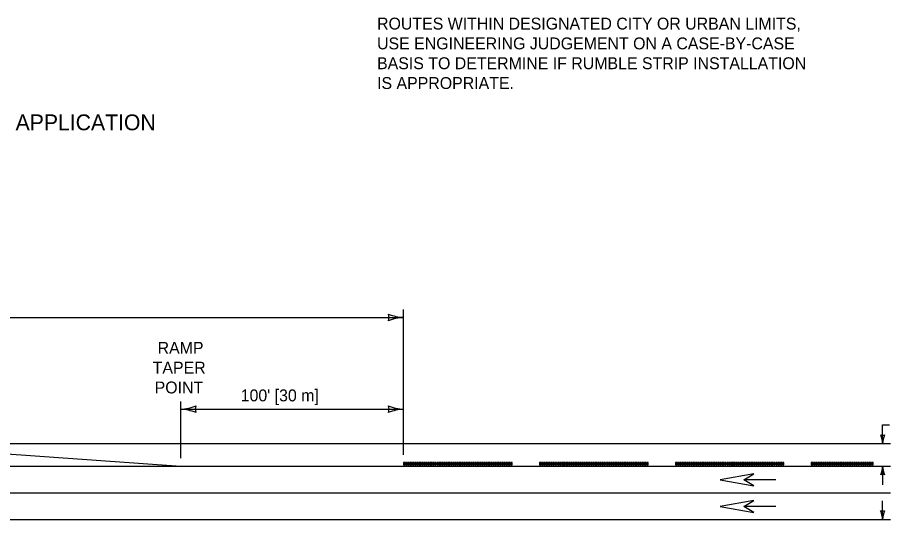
# Model space of a CAD drawing. Extents: x 49991.4 to 50021, y 49987.6 to 50011.4.
# Drawn here: x 50008.031 to 50012.439, y 49990.5 to 49993.033 of the extents above; entities that cross this region are included whole.
import ezdxf

# ---------------------------------------------------------------- set-up
doc = ezdxf.new("R2010")
doc.units = 0
for name, color, linetype in [('Level 1', 7, 'Continuous'), ('Level 2', 7, 'Continuous'), ('Level 3', 7, 'Continuous')]:
    doc.layers.add(name, color=color, linetype=linetype)

msp = doc.modelspace()

# ---------------------------------------------------------------- linework, layer by layer
at = {"layer": 'Level 1'}
for p, q in [((50007.0002, 49990.8996), (50008.8555, 49990.7698)), ((50012.4393, 49990.8823), (50007.8935, 49990.8823)), ((50005.9012, 49990.7698), (50012.4393, 49990.7698)), ((50011.8604, 49990.6996), (50011.6978, 49990.6996)), ((50011.8604, 49990.6995), (50011.6978, 49990.6995)), ((50005.9012, 49990.6348), (50012.4393, 49990.6348)), ((50011.8604, 49990.5662), (50011.6978, 49990.5662)), ((50011.8604, 49990.5661), (50011.6978, 49990.5661)), ((50005.9012, 49990.4998), (50012.4393, 49990.4998))]:
    msp.add_line(p, q, dxfattribs=at)
for points in [[(50009.9885, 49990.7868), (50009.9805, 49990.7868), (50009.9805, 49990.7756), (50009.9885, 49990.7756)], [(50009.9997, 49990.7868), (50009.9919, 49990.7868), (50009.9919, 49990.7756), (50009.9997, 49990.7756)], [(50010.0109, 49990.7868), (50010.0031, 49990.7868), (50010.0031, 49990.7756), (50010.0109, 49990.7756)], [(50010.0222, 49990.7868), (50010.0143, 49990.7868), (50010.0143, 49990.7756), (50010.0222, 49990.7756)], [(50010.0335, 49990.7868), (50010.0255, 49990.7868), (50010.0255, 49990.7756), (50010.0335, 49990.7756)], [(50010.0447, 49990.7868), (50010.0369, 49990.7868), (50010.0369, 49990.7756), (50010.0447, 49990.7756)], [(50010.0559, 49990.7868), (50010.0481, 49990.7868), (50010.0481, 49990.7756), (50010.0559, 49990.7756)], [(50010.0672, 49990.7868), (50010.0593, 49990.7868), (50010.0593, 49990.7756), (50010.0672, 49990.7756)], [(50010.0785, 49990.7868), (50010.0705, 49990.7868), (50010.0705, 49990.7756), (50010.0785, 49990.7756)], [(50010.0897, 49990.7868), (50010.0819, 49990.7868), (50010.0819, 49990.7756), (50010.0897, 49990.7756)], [(50010.1009, 49990.7868), (50010.0931, 49990.7868), (50010.0931, 49990.7756), (50010.1009, 49990.7756)], [(50010.1122, 49990.7868), (50010.1043, 49990.7868), (50010.1043, 49990.7756), (50010.1122, 49990.7756)], [(50010.1235, 49990.7868), (50010.1155, 49990.7868), (50010.1155, 49990.7756), (50010.1235, 49990.7756)], [(50010.1347, 49990.7868), (50010.1269, 49990.7868), (50010.1269, 49990.7756), (50010.1347, 49990.7756)], [(50010.1459, 49990.7868), (50010.1381, 49990.7868), (50010.1381, 49990.7756), (50010.1459, 49990.7756)], [(50010.1572, 49990.7868), (50010.1493, 49990.7868), (50010.1493, 49990.7756), (50010.1572, 49990.7756)], [(50010.1685, 49990.7868), (50010.1605, 49990.7868), (50010.1605, 49990.7756), (50010.1685, 49990.7756)], [(50010.1797, 49990.7868), (50010.1719, 49990.7868), (50010.1719, 49990.7756), (50010.1797, 49990.7756)], [(50010.1909, 49990.7868), (50010.1831, 49990.7868), (50010.1831, 49990.7756), (50010.1909, 49990.7756)], [(50010.2022, 49990.7868), (50010.1943, 49990.7868), (50010.1943, 49990.7756), (50010.2022, 49990.7756)], [(50010.2135, 49990.7868), (50010.2055, 49990.7868), (50010.2055, 49990.7756), (50010.2135, 49990.7756)], [(50010.2247, 49990.7868), (50010.2169, 49990.7868), (50010.2169, 49990.7756), (50010.2247, 49990.7756)], [(50010.2359, 49990.7868), (50010.2281, 49990.7868), (50010.2281, 49990.7756), (50010.2359, 49990.7756)], [(50010.2472, 49990.7868), (50010.2393, 49990.7868), (50010.2393, 49990.7756), (50010.2472, 49990.7756)], [(50010.2585, 49990.7868), (50010.2505, 49990.7868), (50010.2505, 49990.7756), (50010.2585, 49990.7756)], [(50010.2697, 49990.7868), (50010.2619, 49990.7868), (50010.2619, 49990.7756), (50010.2697, 49990.7756)], [(50010.2809, 49990.7868), (50010.2731, 49990.7868), (50010.2731, 49990.7756), (50010.2809, 49990.7756)], [(50010.2922, 49990.7868), (50010.2843, 49990.7868), (50010.2843, 49990.7756), (50010.2922, 49990.7756)], [(50010.3035, 49990.7868), (50010.2955, 49990.7868), (50010.2955, 49990.7756), (50010.3035, 49990.7756)], [(50010.3147, 49990.7868), (50010.3069, 49990.7868), (50010.3069, 49990.7756), (50010.3147, 49990.7756)], [(50010.3259, 49990.7868), (50010.3181, 49990.7868), (50010.3181, 49990.7756), (50010.3259, 49990.7756)], [(50010.3372, 49990.7868), (50010.3293, 49990.7868), (50010.3293, 49990.7756), (50010.3372, 49990.7756)], [(50010.3485, 49990.7868), (50010.3405, 49990.7868), (50010.3405, 49990.7756), (50010.3485, 49990.7756)], [(50010.3597, 49990.7868), (50010.3519, 49990.7868), (50010.3519, 49990.7756), (50010.3597, 49990.7756)], [(50010.3709, 49990.7868), (50010.3631, 49990.7868), (50010.3631, 49990.7756), (50010.3709, 49990.7756)], [(50010.3822, 49990.7868), (50010.3743, 49990.7868), (50010.3743, 49990.7756), (50010.3822, 49990.7756)], [(50010.3935, 49990.7868), (50010.3855, 49990.7868), (50010.3855, 49990.7756), (50010.3935, 49990.7756)], [(50010.4047, 49990.7868), (50010.3969, 49990.7868), (50010.3969, 49990.7756), (50010.4047, 49990.7756)], [(50010.4159, 49990.7868), (50010.4081, 49990.7868), (50010.4081, 49990.7756), (50010.4159, 49990.7756)], [(50010.4272, 49990.7868), (50010.4193, 49990.7868), (50010.4193, 49990.7756), (50010.4272, 49990.7756)], [(50010.4385, 49990.7868), (50010.4305, 49990.7868), (50010.4305, 49990.7756), (50010.4385, 49990.7756)], [(50010.4497, 49990.7868), (50010.4419, 49990.7868), (50010.4419, 49990.7756), (50010.4497, 49990.7756)], [(50010.4609, 49990.7868), (50010.4531, 49990.7868), (50010.4531, 49990.7756), (50010.4609, 49990.7756)], [(50010.4722, 49990.7868), (50010.4643, 49990.7868), (50010.4643, 49990.7756), (50010.4722, 49990.7756)], [(50010.4835, 49990.7868), (50010.4755, 49990.7868), (50010.4755, 49990.7756), (50010.4835, 49990.7756)], [(50010.4947, 49990.7868), (50010.4869, 49990.7868), (50010.4869, 49990.7756), (50010.4947, 49990.7756)], [(50010.5059, 49990.7868), (50010.4981, 49990.7868), (50010.4981, 49990.7756), (50010.5059, 49990.7756)], [(50010.5172, 49990.7868), (50010.5093, 49990.7868), (50010.5093, 49990.7756), (50010.5172, 49990.7756)], [(50010.5285, 49990.7868), (50010.5205, 49990.7868), (50010.5205, 49990.7756), (50010.5285, 49990.7756)], [(50010.6747, 49990.7868), (50010.6669, 49990.7868), (50010.6669, 49990.7756), (50010.6747, 49990.7756)], [(50010.6859, 49990.7868), (50010.6781, 49990.7868), (50010.6781, 49990.7756), (50010.6859, 49990.7756)], [(50010.6972, 49990.7868), (50010.6893, 49990.7868), (50010.6893, 49990.7756), (50010.6972, 49990.7756)], [(50010.7085, 49990.7868), (50010.7005, 49990.7868), (50010.7005, 49990.7756), (50010.7085, 49990.7756)], [(50010.7197, 49990.7868), (50010.7119, 49990.7868), (50010.7119, 49990.7756), (50010.7197, 49990.7756)], [(50010.7309, 49990.7868), (50010.7231, 49990.7868), (50010.7231, 49990.7756), (50010.7309, 49990.7756)], [(50010.7422, 49990.7868), (50010.7343, 49990.7868), (50010.7343, 49990.7756), (50010.7422, 49990.7756)], [(50010.7535, 49990.7868), (50010.7455, 49990.7868), (50010.7455, 49990.7756), (50010.7535, 49990.7756)], [(50010.7647, 49990.7868), (50010.7569, 49990.7868), (50010.7569, 49990.7756), (50010.7647, 49990.7756)], [(50010.7759, 49990.7868), (50010.7681, 49990.7868), (50010.7681, 49990.7756), (50010.7759, 49990.7756)], [(50010.7872, 49990.7868), (50010.7793, 49990.7868), (50010.7793, 49990.7756), (50010.7872, 49990.7756)], [(50010.7985, 49990.7868), (50010.7905, 49990.7868), (50010.7905, 49990.7756), (50010.7985, 49990.7756)], [(50010.8097, 49990.7868), (50010.8019, 49990.7868), (50010.8019, 49990.7756), (50010.8097, 49990.7756)], [(50010.8209, 49990.7868), (50010.8131, 49990.7868), (50010.8131, 49990.7756), (50010.8209, 49990.7756)], [(50010.8322, 49990.7868), (50010.8243, 49990.7868), (50010.8243, 49990.7756), (50010.8322, 49990.7756)], [(50010.8435, 49990.7868), (50010.8355, 49990.7868), (50010.8355, 49990.7756), (50010.8435, 49990.7756)], [(50010.8547, 49990.7868), (50010.8469, 49990.7868), (50010.8469, 49990.7756), (50010.8547, 49990.7756)], [(50010.8659, 49990.7868), (50010.8581, 49990.7868), (50010.8581, 49990.7756), (50010.8659, 49990.7756)], [(50010.8772, 49990.7868), (50010.8693, 49990.7868), (50010.8693, 49990.7756), (50010.8772, 49990.7756)], [(50010.8885, 49990.7868), (50010.8805, 49990.7868), (50010.8805, 49990.7756), (50010.8885, 49990.7756)], [(50010.8997, 49990.7868), (50010.8919, 49990.7868), (50010.8919, 49990.7756), (50010.8997, 49990.7756)], [(50010.9109, 49990.7868), (50010.9031, 49990.7868), (50010.9031, 49990.7756), (50010.9109, 49990.7756)], [(50010.9222, 49990.7868), (50010.9143, 49990.7868), (50010.9143, 49990.7756), (50010.9222, 49990.7756)], [(50010.9335, 49990.7868), (50010.9255, 49990.7868), (50010.9255, 49990.7756), (50010.9335, 49990.7756)], [(50010.9447, 49990.7868), (50010.9369, 49990.7868), (50010.9369, 49990.7756), (50010.9447, 49990.7756)], [(50010.9559, 49990.7868), (50010.9481, 49990.7868), (50010.9481, 49990.7756), (50010.9559, 49990.7756)], [(50010.9672, 49990.7868), (50010.9593, 49990.7868), (50010.9593, 49990.7756), (50010.9672, 49990.7756)], [(50010.9785, 49990.7868), (50010.9705, 49990.7868), (50010.9705, 49990.7756), (50010.9785, 49990.7756)], [(50010.9897, 49990.7868), (50010.9819, 49990.7868), (50010.9819, 49990.7756), (50010.9897, 49990.7756)], [(50011.0009, 49990.7868), (50010.9931, 49990.7868), (50010.9931, 49990.7756), (50011.0009, 49990.7756)], [(50011.0122, 49990.7868), (50011.0043, 49990.7868), (50011.0043, 49990.7756), (50011.0122, 49990.7756)], [(50011.0235, 49990.7868), (50011.0155, 49990.7868), (50011.0155, 49990.7756), (50011.0235, 49990.7756)], [(50011.0347, 49990.7868), (50011.0269, 49990.7868), (50011.0269, 49990.7756), (50011.0347, 49990.7756)], [(50011.0459, 49990.7868), (50011.0381, 49990.7868), (50011.0381, 49990.7756), (50011.0459, 49990.7756)], [(50011.0572, 49990.7868), (50011.0493, 49990.7868), (50011.0493, 49990.7756), (50011.0572, 49990.7756)], [(50011.0685, 49990.7868), (50011.0605, 49990.7868), (50011.0605, 49990.7756), (50011.0685, 49990.7756)], [(50011.0797, 49990.7868), (50011.0719, 49990.7868), (50011.0719, 49990.7756), (50011.0797, 49990.7756)], [(50011.0909, 49990.7868), (50011.0831, 49990.7868), (50011.0831, 49990.7756), (50011.0909, 49990.7756)], [(50011.1022, 49990.7868), (50011.0943, 49990.7868), (50011.0943, 49990.7756), (50011.1022, 49990.7756)], [(50011.1135, 49990.7868), (50011.1055, 49990.7868), (50011.1055, 49990.7756), (50011.1135, 49990.7756)], [(50011.1247, 49990.7868), (50011.1169, 49990.7868), (50011.1169, 49990.7756), (50011.1247, 49990.7756)], [(50011.1359, 49990.7868), (50011.1281, 49990.7868), (50011.1281, 49990.7756), (50011.1359, 49990.7756)], [(50011.1472, 49990.7868), (50011.1393, 49990.7868), (50011.1393, 49990.7756), (50011.1472, 49990.7756)], [(50011.1585, 49990.7868), (50011.1505, 49990.7868), (50011.1505, 49990.7756), (50011.1585, 49990.7756)], [(50011.1697, 49990.7868), (50011.1619, 49990.7868), (50011.1619, 49990.7756), (50011.1697, 49990.7756)], [(50011.1809, 49990.7868), (50011.1731, 49990.7868), (50011.1731, 49990.7756), (50011.1809, 49990.7756)], [(50011.1922, 49990.7868), (50011.1843, 49990.7868), (50011.1843, 49990.7756), (50011.1922, 49990.7756)], [(50011.2035, 49990.7868), (50011.1955, 49990.7868), (50011.1955, 49990.7756), (50011.2035, 49990.7756)], [(50011.2147, 49990.7868), (50011.2069, 49990.7868), (50011.2069, 49990.7756), (50011.2147, 49990.7756)], [(50011.3609, 49990.7868), (50011.3531, 49990.7868), (50011.3531, 49990.7756), (50011.3609, 49990.7756)], [(50011.3722, 49990.7868), (50011.3643, 49990.7868), (50011.3643, 49990.7756), (50011.3722, 49990.7756)], [(50011.3835, 49990.7868), (50011.3755, 49990.7868), (50011.3755, 49990.7756), (50011.3835, 49990.7756)], [(50011.3947, 49990.7868), (50011.3869, 49990.7868), (50011.3869, 49990.7756), (50011.3947, 49990.7756)], [(50011.4059, 49990.7868), (50011.3981, 49990.7868), (50011.3981, 49990.7756), (50011.4059, 49990.7756)], [(50011.4172, 49990.7868), (50011.4093, 49990.7868), (50011.4093, 49990.7756), (50011.4172, 49990.7756)], [(50011.4285, 49990.7868), (50011.4205, 49990.7868), (50011.4205, 49990.7756), (50011.4285, 49990.7756)], [(50011.4397, 49990.7868), (50011.4319, 49990.7868), (50011.4319, 49990.7756), (50011.4397, 49990.7756)], [(50011.4509, 49990.7868), (50011.4431, 49990.7868), (50011.4431, 49990.7756), (50011.4509, 49990.7756)], [(50011.4622, 49990.7868), (50011.4543, 49990.7868), (50011.4543, 49990.7756), (50011.4622, 49990.7756)], [(50011.4735, 49990.7868), (50011.4655, 49990.7868), (50011.4655, 49990.7756), (50011.4735, 49990.7756)], [(50011.4847, 49990.7868), (50011.4769, 49990.7868), (50011.4769, 49990.7756), (50011.4847, 49990.7756)], [(50011.4959, 49990.7868), (50011.4881, 49990.7868), (50011.4881, 49990.7756), (50011.4959, 49990.7756)], [(50011.5072, 49990.7868), (50011.4993, 49990.7868), (50011.4993, 49990.7756), (50011.5072, 49990.7756)], [(50011.5185, 49990.7868), (50011.5105, 49990.7868), (50011.5105, 49990.7756), (50011.5185, 49990.7756)], [(50011.5297, 49990.7868), (50011.5219, 49990.7868), (50011.5219, 49990.7756), (50011.5297, 49990.7756)], [(50011.5409, 49990.7868), (50011.5331, 49990.7868), (50011.5331, 49990.7756), (50011.5409, 49990.7756)], [(50011.5522, 49990.7868), (50011.5443, 49990.7868), (50011.5443, 49990.7756), (50011.5522, 49990.7756)], [(50011.5635, 49990.7868), (50011.5555, 49990.7868), (50011.5555, 49990.7756), (50011.5635, 49990.7756)], [(50011.5747, 49990.7868), (50011.5669, 49990.7868), (50011.5669, 49990.7756), (50011.5747, 49990.7756)], [(50011.5859, 49990.7868), (50011.5781, 49990.7868), (50011.5781, 49990.7756), (50011.5859, 49990.7756)], [(50011.5972, 49990.7868), (50011.5893, 49990.7868), (50011.5893, 49990.7756), (50011.5972, 49990.7756)], [(50011.6085, 49990.7868), (50011.6005, 49990.7868), (50011.6005, 49990.7756), (50011.6085, 49990.7756)], [(50011.6197, 49990.7868), (50011.6119, 49990.7868), (50011.6119, 49990.7756), (50011.6197, 49990.7756)], [(50011.6309, 49990.7868), (50011.6231, 49990.7868), (50011.6231, 49990.7756), (50011.6309, 49990.7756)], [(50011.6422, 49990.7868), (50011.6343, 49990.7868), (50011.6343, 49990.7756), (50011.6422, 49990.7756)], [(50011.6535, 49990.7868), (50011.6455, 49990.7868), (50011.6455, 49990.7756), (50011.6535, 49990.7756)], [(50011.6647, 49990.7868), (50011.6569, 49990.7868), (50011.6569, 49990.7756), (50011.6647, 49990.7756)], [(50011.6759, 49990.7868), (50011.6681, 49990.7868), (50011.6681, 49990.7756), (50011.6759, 49990.7756)], [(50011.6872, 49990.7868), (50011.6793, 49990.7868), (50011.6793, 49990.7756), (50011.6872, 49990.7756)], [(50011.6985, 49990.7868), (50011.6905, 49990.7868), (50011.6905, 49990.7756), (50011.6985, 49990.7756)], [(50011.7097, 49990.7868), (50011.7019, 49990.7868), (50011.7019, 49990.7756), (50011.7097, 49990.7756)], [(50011.7209, 49990.7868), (50011.7131, 49990.7868), (50011.7131, 49990.7756), (50011.7209, 49990.7756)], [(50011.7322, 49990.7868), (50011.7243, 49990.7868), (50011.7243, 49990.7756), (50011.7322, 49990.7756)], [(50011.7435, 49990.7868), (50011.7355, 49990.7868), (50011.7355, 49990.7756), (50011.7435, 49990.7756)], [(50011.7547, 49990.7868), (50011.7469, 49990.7868), (50011.7469, 49990.7756), (50011.7547, 49990.7756)], [(50011.7659, 49990.7868), (50011.7581, 49990.7868), (50011.7581, 49990.7756), (50011.7659, 49990.7756)], [(50011.7772, 49990.7868), (50011.7693, 49990.7868), (50011.7693, 49990.7756), (50011.7772, 49990.7756)], [(50011.7885, 49990.7868), (50011.7805, 49990.7868), (50011.7805, 49990.7756), (50011.7885, 49990.7756)], [(50011.7997, 49990.7868), (50011.7919, 49990.7868), (50011.7919, 49990.7756), (50011.7997, 49990.7756)], [(50011.8109, 49990.7868), (50011.8031, 49990.7868), (50011.8031, 49990.7756), (50011.8109, 49990.7756)], [(50011.8222, 49990.7868), (50011.8143, 49990.7868), (50011.8143, 49990.7756), (50011.8222, 49990.7756)], [(50011.8335, 49990.7868), (50011.8255, 49990.7868), (50011.8255, 49990.7756), (50011.8335, 49990.7756)], [(50011.8447, 49990.7868), (50011.8369, 49990.7868), (50011.8369, 49990.7756), (50011.8447, 49990.7756)], [(50011.8559, 49990.7868), (50011.8481, 49990.7868), (50011.8481, 49990.7756), (50011.8559, 49990.7756)], [(50011.8672, 49990.7868), (50011.8593, 49990.7868), (50011.8593, 49990.7756), (50011.8672, 49990.7756)], [(50011.8785, 49990.7868), (50011.8705, 49990.7868), (50011.8705, 49990.7756), (50011.8785, 49990.7756)], [(50011.8897, 49990.7868), (50011.8819, 49990.7868), (50011.8819, 49990.7756), (50011.8897, 49990.7756)], [(50011.9009, 49990.7868), (50011.8931, 49990.7868), (50011.8931, 49990.7756), (50011.9009, 49990.7756)], [(50012.0472, 49990.7868), (50012.0393, 49990.7868), (50012.0393, 49990.7756), (50012.0472, 49990.7756)], [(50012.0585, 49990.7868), (50012.0505, 49990.7868), (50012.0505, 49990.7756), (50012.0585, 49990.7756)], [(50012.0697, 49990.7868), (50012.0619, 49990.7868), (50012.0619, 49990.7756), (50012.0697, 49990.7756)], [(50012.0809, 49990.7868), (50012.0731, 49990.7868), (50012.0731, 49990.7756), (50012.0809, 49990.7756)], [(50012.0922, 49990.7868), (50012.0843, 49990.7868), (50012.0843, 49990.7756), (50012.0922, 49990.7756)], [(50012.1035, 49990.7868), (50012.0955, 49990.7868), (50012.0955, 49990.7756), (50012.1035, 49990.7756)], [(50012.1147, 49990.7868), (50012.1069, 49990.7868), (50012.1069, 49990.7756), (50012.1147, 49990.7756)], [(50012.1259, 49990.7868), (50012.1181, 49990.7868), (50012.1181, 49990.7756), (50012.1259, 49990.7756)], [(50012.1372, 49990.7868), (50012.1293, 49990.7868), (50012.1293, 49990.7756), (50012.1372, 49990.7756)], [(50012.1485, 49990.7868), (50012.1405, 49990.7868), (50012.1405, 49990.7756), (50012.1485, 49990.7756)], [(50012.1597, 49990.7868), (50012.1519, 49990.7868), (50012.1519, 49990.7756), (50012.1597, 49990.7756)], [(50012.1709, 49990.7868), (50012.1631, 49990.7868), (50012.1631, 49990.7756), (50012.1709, 49990.7756)], [(50012.1822, 49990.7868), (50012.1743, 49990.7868), (50012.1743, 49990.7756), (50012.1822, 49990.7756)], [(50012.1935, 49990.7868), (50012.1855, 49990.7868), (50012.1855, 49990.7756), (50012.1935, 49990.7756)], [(50012.2047, 49990.7868), (50012.1969, 49990.7868), (50012.1969, 49990.7756), (50012.2047, 49990.7756)], [(50012.2159, 49990.7868), (50012.2081, 49990.7868), (50012.2081, 49990.7756), (50012.2159, 49990.7756)], [(50012.2272, 49990.7868), (50012.2192, 49990.7868), (50012.2192, 49990.7756), (50012.2272, 49990.7756)], [(50012.2384, 49990.7868), (50012.2306, 49990.7868), (50012.2306, 49990.7756), (50012.2384, 49990.7756)], [(50012.2496, 49990.7868), (50012.2418, 49990.7868), (50012.2418, 49990.7756), (50012.2496, 49990.7756)], [(50012.2609, 49990.7868), (50012.253, 49990.7868), (50012.253, 49990.7756), (50012.2609, 49990.7756)], [(50012.2722, 49990.7868), (50012.2642, 49990.7868), (50012.2642, 49990.7756), (50012.2722, 49990.7756)], [(50012.2834, 49990.7868), (50012.2756, 49990.7868), (50012.2756, 49990.7756), (50012.2834, 49990.7756)], [(50012.2946, 49990.7868), (50012.2868, 49990.7868), (50012.2868, 49990.7756), (50012.2946, 49990.7756)], [(50012.3059, 49990.7868), (50012.298, 49990.7868), (50012.298, 49990.7756), (50012.3059, 49990.7756)], [(50012.3172, 49990.7868), (50012.3092, 49990.7868), (50012.3092, 49990.7756), (50012.3172, 49990.7756)], [(50012.3284, 49990.7868), (50012.3206, 49990.7868), (50012.3206, 49990.7756), (50012.3284, 49990.7756)], [(50012.3396, 49990.7868), (50012.3318, 49990.7868), (50012.3318, 49990.7756), (50012.3396, 49990.7756)], [(50012.3508, 49990.7868), (50012.343, 49990.7868), (50012.343, 49990.7756), (50012.3508, 49990.7756)], [(50011.7498, 49990.7296), (50011.5796, 49990.6996), (50011.7498, 49990.6694), (50011.698, 49990.6996)], [(50011.7498, 49990.5962), (50011.5796, 49990.5662), (50011.7498, 49990.536), (50011.698, 49990.5662)]]:
    msp.add_lwpolyline(points, close=True, dxfattribs=at)
at = {"layer": 'Level 3'}
for p, q in [((50009.9805, 49990.8268), (50009.9805, 49991.5598)), ((50004.638, 49991.5198), (50009.9805, 49991.5198)), ((50008.8555, 49990.8098), (50008.8555, 49991.0961)), ((50008.8555, 49991.0561), (50009.9805, 49991.0561)), ((50012.3993, 49990.8823), (50012.3993, 49990.9773)), ((50012.3993, 49990.9773), (50012.4343, 49990.9773)), ((50012.3993, 49990.7698), (50012.3993, 49990.6748)), ((50012.399, 49990.4998), (50012.399, 49990.5948))]:
    msp.add_line(p, q, dxfattribs=at)
for centre, radius, start, end in [((50009.9897, 49991.7419), 0.2223, 247.456, 267.6395), ((50009.8523, 49991.5198), 0.0548, 342.1388, 17.8612), ((50009.992, 49991.2871), 0.233, 92.8273, 112.0772), ((50008.844, 49991.2888), 0.233, 272.8273, 292.0772), ((50008.8463, 49990.834), 0.2223, 67.456, 87.6395), ((50008.9837, 49991.0561), 0.0548, 162.1388, 197.8612), ((50009.9897, 49991.2782), 0.2223, 247.456, 267.6395), ((50009.8523, 49991.0561), 0.0548, 342.1388, 17.8612), ((50009.992, 49990.8234), 0.233, 92.8273, 112.0772), ((50012.3993, 49990.9571), 0.032, 252.1388, 287.8612), ((50012.2636, 49990.8756), 0.1359, 2.8273, 22.0772), ((50012.5289, 49990.877), 0.1297, 157.456, 177.6395), ((50012.2697, 49990.7751), 0.1297, 337.456, 357.6395), ((50012.535, 49990.7765), 0.1359, 182.8273, 202.0772), ((50012.3993, 49990.695), 0.032, 72.1388, 107.8612), ((50012.399, 49990.5746), 0.032, 252.1388, 287.8612), ((50012.2633, 49990.4931), 0.1359, 2.8273, 22.0772), ((50012.5286, 49990.4945), 0.1297, 157.456, 177.6395)]:
    msp.add_arc(centre, radius, start, end, dxfattribs=at)

# ---------------------------------------------------------------- texts
at = {"layer": 'Level 2'}
for s, height, p in [('ROUTES WITHIN DESIGNATED CITY OR URBAN LIMITS,', 0.06, (50009.8467, 49992.9722)), ('USE ENGINEERING JUDGEMENT ON A CASE-BY-CASE', 0.06, (50009.8467, 49992.8722)), ('BASIS TO DETERMINE IF RUMBLE STRIP INSTALLATION', 0.06, (50009.8467, 49992.7722)), ('IS APPROPRIATE.', 0.06, (50009.8467, 49992.6722)), ('TYPICAL APPLICATION', 0.08, (50007.546, 49992.4639)), ('RAMP', 0.06, (50008.7386, 49991.3361)), ('TAPER', 0.06, (50008.7138, 49991.2361)), ('POINT', 0.06, (50008.7236, 49991.1361)), ("100' [30 m]", 0.06, (50009.1582, 49991.0961))]:
    msp.add_text(s, height=height, dxfattribs=at).set_placement(p)

doc.saveas('drawing.dxf')
